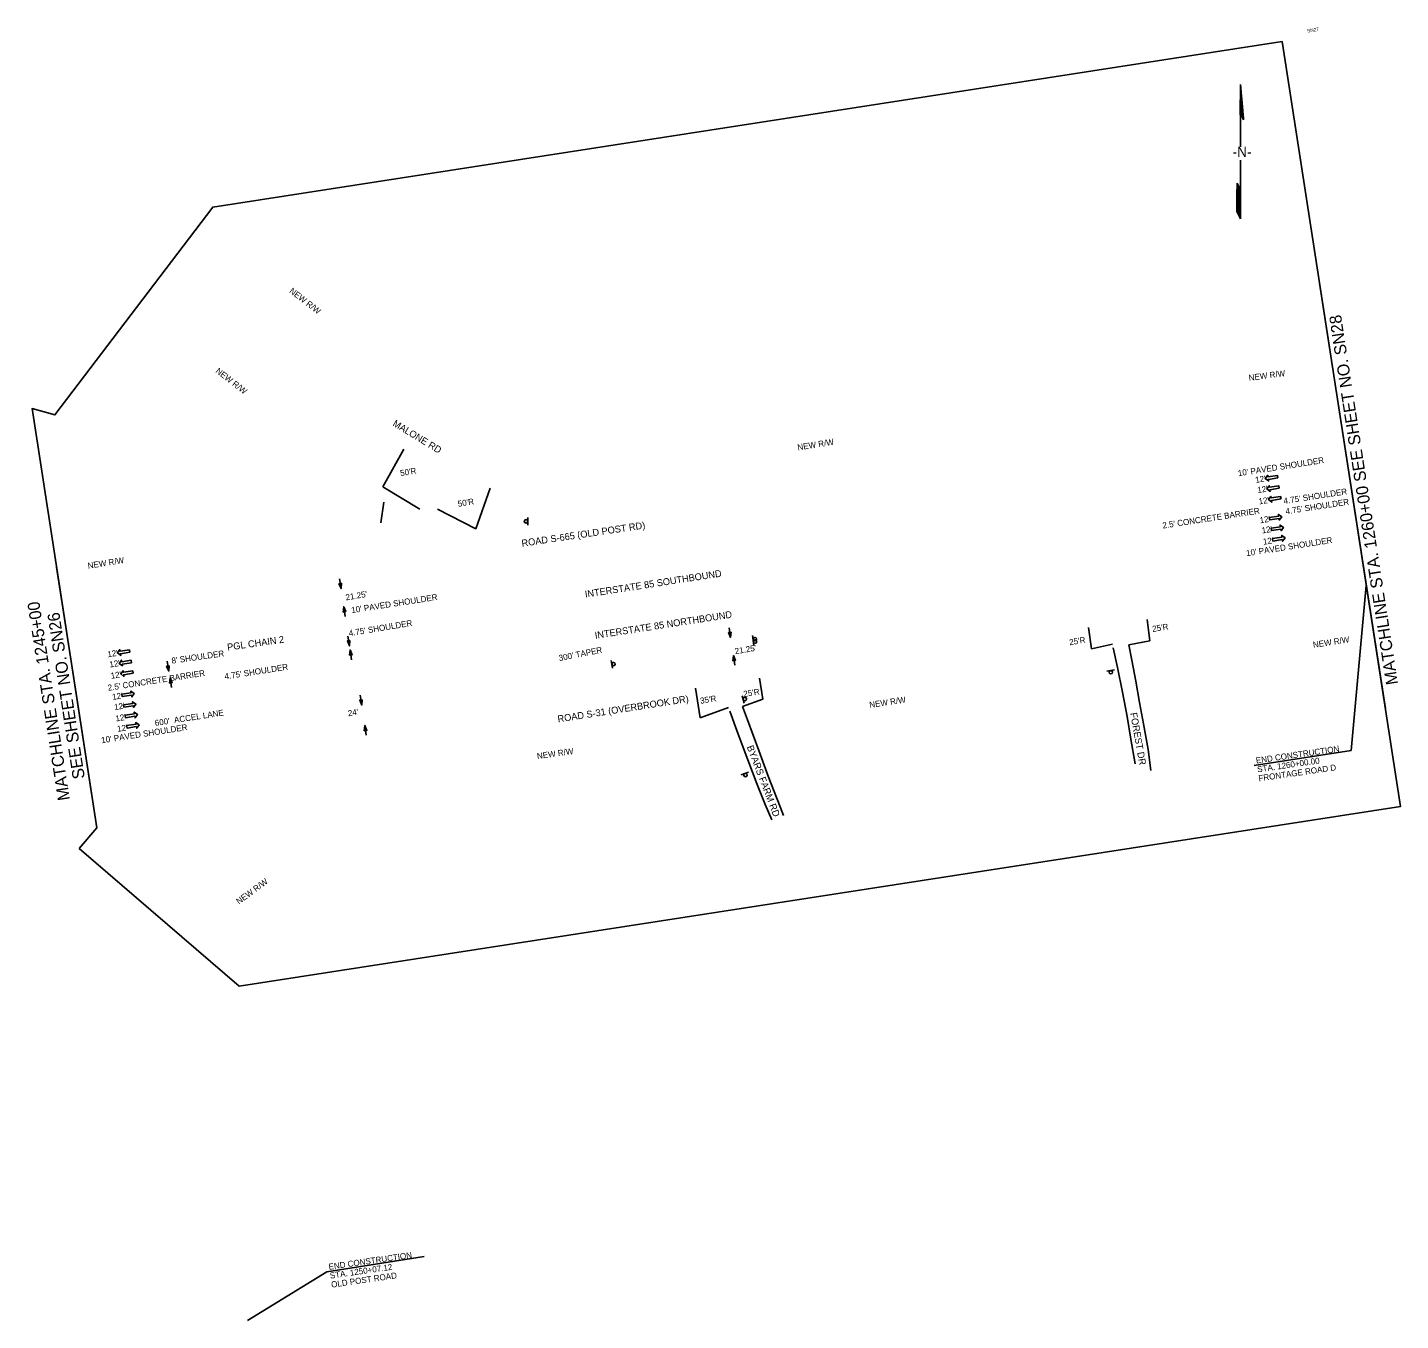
# Model space of a CAD drawing. Extents: x 1773824 to 1775419, y 1178927 to 1180428.
import ezdxf

# ---------------------------------------------------------------- set-up
doc = ezdxf.new("R2010")
doc.units = 0
for name, color, linetype in [('RD_DTM_BkLn1', 7, 'Continuous'), ('RD_DTM_BkLn2', 7, 'Continuous'), ('RD_EX_Bldg', 7, 'Continuous'), ('RD_EX_Conc', 7, 'Continuous'), ('RD_EX_DR_Inlet_txCode', 7, 'Continuous'), ('RD_EX_Driveway', 7, 'Continuous'), ('RD_EX_Fence_ChLk', 7, 'Continuous'), ('RD_EX_H2O', 7, 'Continuous'), ('RD_EX_Road', 7, 'Continuous'), ('RD_EX_SU_Elec', 7, 'Continuous'), ('RD_SMD_Locator', 7, 'Continuous')]:
    doc.layers.add(name, color=color, linetype=linetype)

# ---------------------------------------------------------------- blocks, each defined once
blk = doc.blocks.new('SARRW2')
at = {"layer": 'RD_EX_Driveway'}
blk.add_lwpolyline([(-12, 1.2), (-12, -1.2), (-2.8, -1.2), (-2.8, -2.8), (0, 0), (-2.8, 2.8), (-2.8, 1.2)], close=True, dxfattribs=at)
blk = doc.blocks.new('AH')
at = {"layer": 'RD_EX_Bldg'}
blk.add_lwpolyline([(-6, 1.5), (0, 0), (-6, -1.5)], close=True, dxfattribs=at)
blk = doc.blocks.new('NA5')
at = {"layer": 'RD_DTM_BkLn1'}
for p, q in [((47.5, 65.9), (26.8, 37.4)), ((26.8, 30.6), (47.5, 65.9)), ((27.2, 37.5), (14.5, 19.8)), ((28.1, 38.3), (26.8, 30.6)), ((14.5, 19.8), (5.5, 7.2)), ((-3.5, -5.3), (-18.5, -26.3)), ((-18.5, -26.3), (-43.3, -60.9)), ((-30.6, -36.2), (-22.3, -24.7)), ((-22.3, -24.7), (-24, -34)), ((-41.6, -51.6), (-30.6, -36.2)), ((-43.3, -60.9), (-41.6, -51.6))]:
    blk.add_line(p, q, dxfattribs=at)
for points in [[(27.4, 37.8), (47.4, 65.8)], [(27.6, 37.9), (46.9, 64.9)], [(27.8, 38.1), (46.4, 64)], [(27.1, 37.6), (39.2, 54.5)], [(27.5, 34.9), (37.5, 48.8)], [(27.5, 34.7), (36.9, 47.9)], [(27.6, 35.5), (39, 51.5)], [(27.6, 35.3), (38.5, 50.6)], [(27.6, 35.1), (38, 49.7)], [(27.7, 36.2), (40.6, 54.2)], [(27.7, 36), (40.1, 53.3)], [(27.7, 35.8), (39.6, 52.4)], [(27.8, 36.8), (42.2, 56.8)], [(27.8, 36.6), (41.7, 56)], [(27.8, 36.4), (41.1, 55.1)], [(27.9, 37.4), (43.8, 59.5)], [(27.9, 37.2), (43.2, 58.6)], [(27.9, 37), (42.7, 57.7)], [(28, 38.1), (45.3, 62.2)], [(28, 37.9), (44.8, 61.3)], [(28, 37.7), (44.3, 60.4)], [(28.1, 38.3), (45.8, 63.1)], [(26.9, 37.5), (29.9, 41.7)], [(26.9, 31.3), (28.5, 33.6)], [(26.9, 31.1), (28, 32.7)], [(27, 32), (30.1, 36.3)], [(27, 31.8), (29.6, 35.4)], [(27, 31.5), (29.1, 34.5)], [(27.1, 32.6), (31.7, 39)], [(27.1, 32.4), (31.2, 38.1)], [(27.1, 32.2), (30.6, 37.2)], [(27.2, 33.2), (33.3, 41.6)], [(27.2, 33), (32.7, 40.7)], [(27.2, 32.8), (32.2, 39.9)], [(27.3, 33.9), (34.8, 44.3)], [(27.3, 33.7), (34.3, 43.4)], [(27.3, 33.4), (33.8, 42.5)], [(27.4, 34.5), (36.4, 47)], [(27.4, 34.3), (35.9, 46.1)], [(27.4, 34.1), (35.4, 45.2)], [(26.8, 30.7), (27, 30.9)], [(26.9, 30.9), (27.5, 31.8)], [(-42.9, -58.6), (-23.6, -31.7)], [(-42.9, -58.8), (-23.7, -31.9)], [(-42.8, -58.1), (-23.5, -31.2)], [(-42.8, -58.3), (-23.6, -31.4)], [(-42.7, -57.5), (-23.4, -30.6)], [(-42.7, -57.7), (-23.5, -30.8)], [(-42.7, -57.9), (-23.5, -31)], [(-42.6, -57), (-23.3, -30.1)], [(-42.6, -57.2), (-23.4, -30.4)], [(-42.5, -56.4), (-23.2, -29.5)], [(-42.5, -56.6), (-23.2, -29.7)], [(-42.5, -56.8), (-23.3, -29.9)], [(-42.4, -55.9), (-23.1, -29)], [(-42.4, -56.1), (-23.2, -29.3)], [(-42.3, -55.3), (-23, -28.4)], [(-42.3, -55.5), (-23, -28.6)], [(-42.3, -55.7), (-23.1, -28.8)], [(-42.2, -54.8), (-22.9, -27.9)], [(-42.2, -55), (-23, -28.2)], [(-42.1, -54.4), (-22.8, -27.5)], [(-42.1, -54.6), (-22.9, -27.7)], [(-42, -53.7), (-22.7, -26.8)], [(-42, -53.9), (-22.7, -27.1)], [(-42, -54.2), (-22.8, -27.3)], [(-41.9, -53.3), (-22.6, -26.4)], [(-41.9, -53.5), (-22.7, -26.6)], [(-41.8, -52.6), (-22.5, -25.7)], [(-41.8, -52.8), (-22.5, -26)], [(-41.8, -53.1), (-22.6, -26.2)], [(-41.7, -52.2), (-22.4, -25.3)], [(-41.7, -52.4), (-22.5, -25.5)], [(-41.6, -51.7), (-22.3, -24.9)], [(-41.6, -52), (-22.4, -25.1)], [(-43.3, -60.8), (-24, -33.9)], [(-43.2, -60.1), (-23.9, -33.2)], [(-43.2, -60.3), (-23.9, -33.4)], [(-43.2, -60.5), (-24, -33.6)], [(-43.1, -59.7), (-23.8, -32.8)], [(-43.1, -59.9), (-23.9, -33)], [(-43, -59), (-23.7, -32.1)], [(-43, -59.2), (-23.7, -32.3)], [(-43, -59.4), (-23.8, -32.5)]]:
    blk.add_lwpolyline(points, dxfattribs=at)
blk.add_text('-N-', height=11.81, rotation=324.3865, dxfattribs=at).set_placement((-8.8, 3))

msp = doc.modelspace()

# ---------------------------------------------------------------- linework, layer by layer
at = {"layer": 'RD_DTM_BkLn2'}
for points in [[(1775401.4, 1179637.1), (1775324.9, 1180131.2)], [(1773904.9, 1179498.8), (1773880.8, 1179654.7), (1773858.1, 1179801.4)]]:
    msp.add_lwpolyline(points, dxfattribs=at)
at = {"layer": 'RD_EX_DR_Inlet_txCode'}
msp.add_lwpolyline([(1773884.2, 1179474.8), (1773904.9, 1179498.8), (1773829.6, 1179985.5), (1773856.1, 1179978), (1774039.5, 1180219.3), (1775281.5, 1180411.6), (1775419, 1179523.5), (1774070.3, 1179314.7)], close=True, dxfattribs=at)
at = {"layer": 'RD_EX_Fence_ChLk'}
for p, q in [((1774234.5, 1179852.6), (1774238, 1179876.7)), ((1774405.4, 1179849.9), (1774405.3, 1179858.9)), ((1774666.3, 1179721.9), (1774667.8, 1179713)), ((1774666.6, 1179719.1), (1774668, 1179710.2)), ((1774502.3, 1179692.9), (1774503.7, 1179684)), ((1775086.6, 1179682.1), (1775077.8, 1179680.4)), ((1774654.3, 1179652.1), (1774656.6, 1179643.4)), ((1774661.7, 1179563.4), (1774653.3, 1179560.1))]:
    msp.add_line(p, q, dxfattribs=at)
for centre in [(1774403.3, 1179854.5), (1774669.1, 1179717.8), (1774669.3, 1179715), (1774505, 1179688.8), (1775082.5, 1179679.3), (1774657.4, 1179648.3), (1774658.2, 1179559.9)]:
    msp.add_circle(centre, 2, dxfattribs=at)
at = {"layer": 'RD_EX_H2O'}
for p, q in [((1774237.1, 1179894.5), (1774261.2, 1179938.3)), ((1774237.1, 1179894.5), (1774279.9, 1179868.8)), ((1774345, 1179845.9), (1774361.7, 1179893.1)), ((1774345, 1179845.9), (1774300.5, 1179868.8)), ((1774188.4, 1179776.4), (1774186.6, 1179787.7)), ((1775379, 1179780.2), (1775361.8, 1179588.6)), ((1774191.6, 1179755.4), (1774193.2, 1179744)), ((1775127.9, 1179715.9), (1775124.7, 1179740.7)), ((1774640.9, 1179719.7), (1774639.1, 1179731)), ((1775060, 1179706.5), (1775056.4, 1179731.3)), ((1774198.2, 1179709.9), (1774196.5, 1179721.2)), ((1775060, 1179706.5), (1775084.4, 1179712)), ((1775127.9, 1179715.9), (1775103.4, 1179711.1)), ((1773988.4, 1179680.7), (1773986.4, 1179692)), ((1774199, 1179705.2), (1774200.6, 1179693.8)), ((1774644.1, 1179698.7), (1774645.7, 1179687.4)), ((1773989.8, 1179672.8), (1773991.6, 1179661.5)), ((1774605.6, 1179626.4), (1774600.2, 1179661)), ((1774678.4, 1179647.9), (1774674.6, 1179672.6)), ((1774212.5, 1179641.2), (1774210.7, 1179652.6)), ((1774678.4, 1179647.9), (1774654.9, 1179639.4)), ((1774605.6, 1179626.4), (1774638.5, 1179638.2)), ((1774216.1, 1179617.5), (1774217.7, 1179606.2)), ((1775249, 1179571.1), (1775361.8, 1179588.6)), ((1774172, 1178983.3), (1774284.8, 1179000.8)), ((1774079.9, 1178926.6), (1774172, 1178983.3))]:
    msp.add_line(p, q, dxfattribs=at)
at = {"layer": 'RD_SMD_Locator'}
for points in [[(1775110.7, 1179573.1), (1775105.9, 1179601.6), (1775101.3, 1179627.9), (1775096.1, 1179656.3), (1775090.4, 1179684.9), (1775085.4, 1179707.6)], [(1775129.1, 1179565.2), (1775126, 1179589.6), (1775120.4, 1179619.4), (1775115.9, 1179644), (1775111.4, 1179668.8), (1775106.8, 1179693.4), (1775103.4, 1179711.1)], [(1774640, 1179634), (1774649.5, 1179607.4), (1774660.9, 1179577.7), (1774671.6, 1179549.1), (1774681.2, 1179525.7), (1774688.7, 1179508)], [(1774654.9, 1179639.4), (1774660.4, 1179624.1), (1774673.5, 1179588.6), (1774684.7, 1179558.6), (1774698.3, 1179523.2), (1774702.4, 1179513.1)]]:
    msp.add_lwpolyline(points, dxfattribs=at)

# ---------------------------------------------------------------- block references
at = {"layer": 'RD_DTM_BkLn2', "rotation": 35.61349782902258}
msp.add_blockref('NA5', (1775232.8, 1180280.4), dxfattribs=at)
at = {"layer": 'RD_EX_Driveway', "xscale": 1.2}
for p, yscale, rotation in [((1775261.9, 1179904.2), 1.2, -171.19998882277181), ((1775263.7, 1179892.1), 1.2, -171.19998882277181), ((1775265.7, 1179879.7), 1.2, -171.19998882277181), ((1775281, 1179859.8), 1.1999999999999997, 8.800011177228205), ((1775283, 1179847.4), 1.1999999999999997, 8.800011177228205), ((1775284.8, 1179835.3), 1.1999999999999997, 8.800011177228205), ((1773928.7, 1179701.7), 1.2, -171.19998882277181), ((1773930.6, 1179689.6), 1.2, -171.19998882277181), ((1773932.5, 1179677.3), 1.2, -171.19998882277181), ((1773948.3, 1179654.6), 1.1999999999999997, 8.800011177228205), ((1773950.2, 1179642.3), 1.1999999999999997, 8.800011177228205), ((1773952.1, 1179630.2), 1.1999999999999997, 8.800011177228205), ((1773953.9, 1179618.1), 1.1999999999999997, 8.800011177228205)]:
    msp.add_blockref('SARRW2', p, dxfattribs=dict(at, yscale=yscale, rotation=rotation))
at = {"layer": 'RD_EX_H2O'}
for p, rotation in [((1774188.4, 1179776.4), -81.19998881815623), ((1774191.6, 1179755.4), 98.04915697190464), ((1774640.9, 1179719.7), -81.19998881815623), ((1774198.2, 1179709.9), -81.19998881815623), ((1774199, 1179705.2), 98.04915697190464), ((1774644.1, 1179698.7), 98.04915697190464), ((1773988.4, 1179680.7), -80.2839901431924), ((1773989.8, 1179672.8), 98.9651556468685), ((1774212.5, 1179641.2), -81.19998881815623), ((1774216.1, 1179617.5), 98.04915697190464)]:
    msp.add_blockref('AH', p, dxfattribs=dict(at, rotation=rotation))

# ---------------------------------------------------------------- texts
at = {"layer": 'RD_DTM_BkLn2'}
for s, p in [('MATCHLINE STA. 1260+00 SEE SHEET NO. SN28', (1775416.2, 1179665.8)), ('MATCHLINE STA. 1245+00', (1773873.6, 1179531.4)), ('SEE SHEET NO. SN26', (1773891, 1179556.4))]:
    msp.add_text(s, height=14, rotation=98.8, dxfattribs=at).set_placement(p)
at = {"layer": 'RD_EX_Conc'}
for rotation, p in [(322.2172, (1774127.8, 1180120.7)), (322.2172, (1774042.1, 1180027.8)), (7.5227, (1775243.1, 1180017.6)), (9.1776, (1774719.1, 1179936.8)), (9.1776, (1773894.8, 1179799.4)), (8.8, (1775317.8, 1179707.6)), (8.522, (1774802.5, 1179637.9)), (8.1514, (1774416.5, 1179578.4)), (36.125, (1774069.8, 1179409.6))]:
    msp.add_text('NEW R/W', height=7, rotation=rotation, dxfattribs=at).set_placement(p)
at = {"layer": 'RD_EX_H2O'}
for s, rotation, p in [("50'R", 9.3833, (1774257.7, 1179906.9)), ("10' PAVED SHOULDER", 8.8, (1775230.6, 1179906.8)), ("12'", 8.8, (1775250.8, 1179899.1)), ("12'", 8.8, (1775253.2, 1179887.3)), ("4.75' SHOULDER", 8.8, (1775283.6, 1179874.6)), ("50'R", 9.3833, (1774324.6, 1179871.3)), ("2.5' CONCRETE BARRIER", 8.8, (1775143, 1179846.1)), ("12'", 8.8, (1775254.7, 1179874.1)), ("4.75' SHOULDER", 8.8, (1775285.9, 1179862.6)), ("12'", 8.8, (1775255.9, 1179852.2)), ("10' PAVED SHOULDER", 8.8, (1775240.2, 1179814)), ("12'", 8.8, (1775258.3, 1179840.4)), ("12'", 8.8, (1775259.8, 1179827.3)), ("21.25'", 9.3833, (1774194.3, 1179762.7)), ("10' PAVED SHOULDER", 8.8, (1774200.9, 1179747.9)), ("4.75' SHOULDER", 9.3833, (1774198, 1179721.1)), ("25'R", 9.3833, (1775131.1, 1179726)), ("300' TAPER", 11.0906, (1774442, 1179692.2)), ("21.25'", 9.3833, (1774646.3, 1179700.2)), ("25'R", 9.3833, (1775034.8, 1179710.6)), ("12'", 8.8, (1773917.6, 1179696.6)), ("12'", 8.8, (1773920, 1179684.8)), ("8' SHOULDER", 8.137, (1773992.1, 1179689.2)), ("2.5' CONCRETE BARRIER", 8.8, (1773918, 1179657.7)), ("12'", 8.8, (1773921.5, 1179671.7)), ("4.75' SHOULDER", 8.8, (1774053.6, 1179670.9)), ("25'R", 9.3833, (1774656.3, 1179650.5)), ("12'", 8.8, (1773923.2, 1179647.1)), ("12'", 8.8, (1773925.5, 1179635.3)), ("35'R", 9.3833, (1774606, 1179642.6)), ("12'", 8.8, (1773927, 1179622.1)), ("600'  ACCEL LANE", 8.8, (1773972.7, 1179616.8)), ("24'", 9.3833, (1774197, 1179628.1)), ("10' PAVED SHOULDER", 8.8, (1773910.5, 1179596.8)), ("12'", 8.8, (1773928.9, 1179610)), ('END CONSTRUCTION', 8.1732, (1775251.5, 1179573.3)), ('STA. 1260+00.00', 8.1732, (1775253, 1179563)), ('FRONTAGE ROAD D', 8.1732, (1775254.5, 1179552.6)), ('END CONSTRUCTION', 8.1732, (1774174.5, 1178985.5)), ('STA. 1250+07.12', 8.1732, (1774176, 1178975.2)), ('OLD POST ROAD', 8.1732, (1774177.5, 1178964.8))]:
    msp.add_text(s, height=7, rotation=rotation, dxfattribs=at).set_placement(p)
at = {"layer": 'RD_EX_Road'}
msp.add_text('SN27', height=4, rotation=8.8, dxfattribs=at).set_placement((1775310.8, 1180422))
at = {"layer": 'RD_EX_SU_Elec'}
for s, rotation, p in [('MALONE RD', 328.6289, (1774247.7, 1179966)), ('ROAD S-665 (OLD POST RD)', 8.4657, (1774398.7, 1179825)), ('INTERSTATE 85 SOUTHBOUND', 8.8, (1774472.3, 1179765.9)), ('INTERSTATE 85 NORTHBOUND', 8.8, (1774483.8, 1179718.1)), ('PGL CHAIN 2', 8.0292, (1774056.8, 1179704.4)), ('ROAD S-31 (OVERBROOK DR)', 8.9115, (1774440.6, 1179621)), ('FOREST DR', 280.0986, (1775104.9, 1179631.8)), ('BYARS FARM RD', 291.0249, (1774659.5, 1179592.7))]:
    msp.add_text(s, height=8, rotation=rotation, dxfattribs=at).set_placement(p)

doc.saveas('drawing.dxf')
